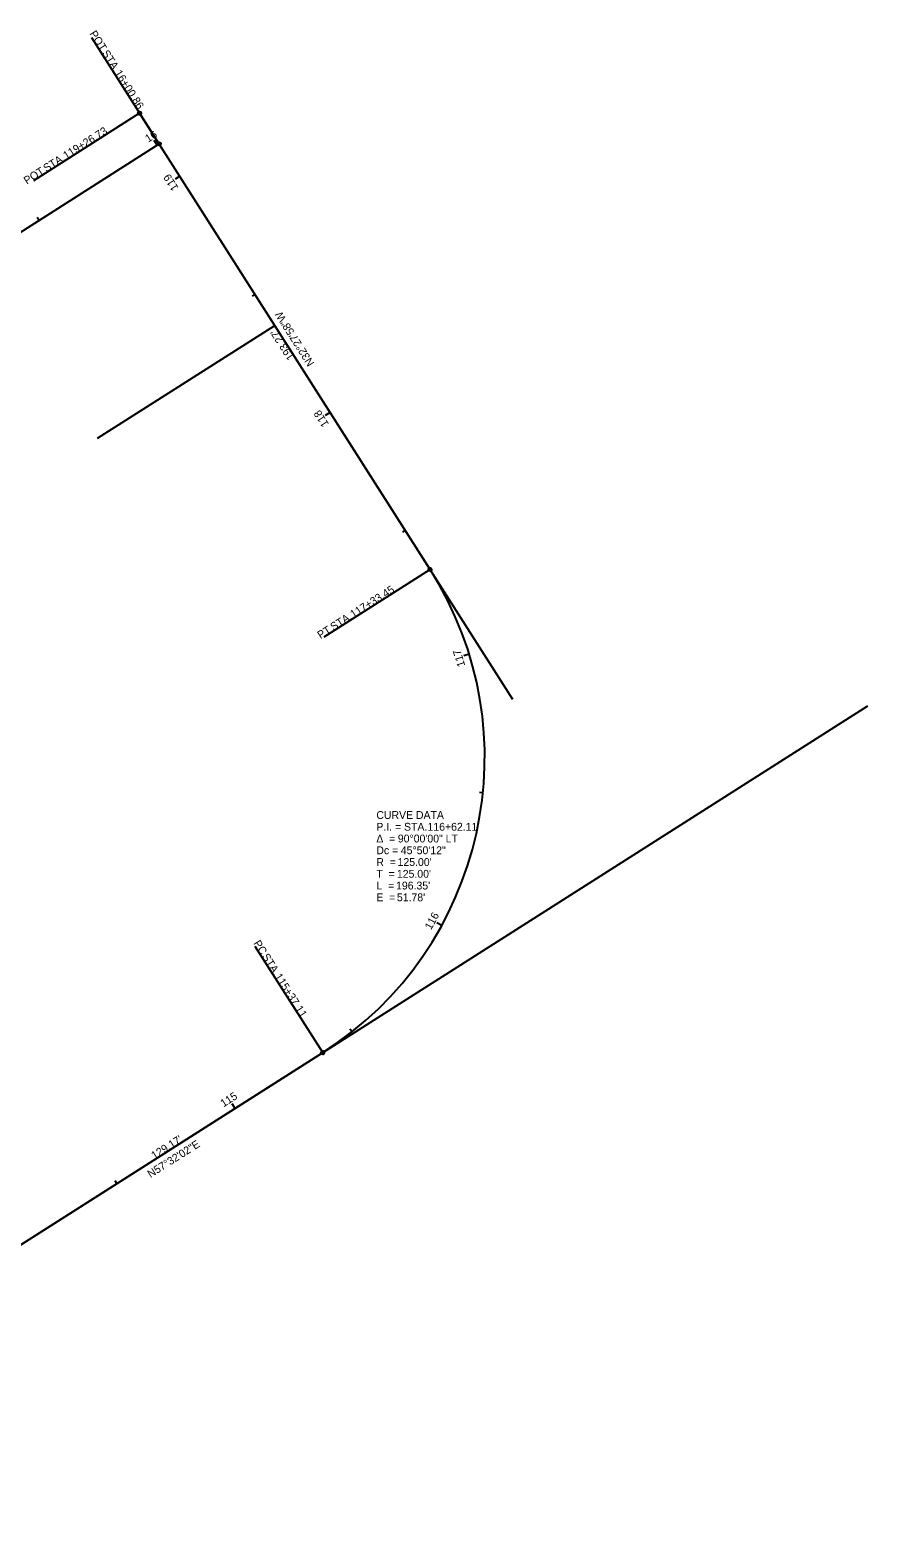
# Model space of a CAD drawing. Extents: x 143938 to 145591, y 512467 to 513276.
# Drawn here: x 145292 to 145591, y 512738 to 513276 of the extents above; entities that cross this region are included whole.
import ezdxf

# ---------------------------------------------------------------- set-up
doc = ezdxf.new("R2010")
doc.units = 0
for name, color, linetype in [('GE_P_Alignment', 7, 'Continuous'), ('GE_P_Alignment_100_Bearings', 7, 'Continuous'), ('GE_P_Alignment_100_Cardinal_Points', 7, 'Continuous'), ('GE_P_Alignment_100_Curve_Data', 7, 'Continuous'), ('GE_P_Alignment_100_Distances', 7, 'Continuous'), ('GE_P_Alignment_100_Stations', 7, 'Continuous'), ('GE_P_Driveway_CL', 7, 'Continuous')]:
    doc.layers.add(name, color=color, linetype=linetype)

msp = doc.modelspace()

# ---------------------------------------------------------------- linework, layer by layer
at = {"layer": 'GE_P_Alignment'}
for p, q in [((145464.37, 513037.37), (145331.09, 513246.84)), ((145434.84, 513083.78), (145331.09, 513246.84)), ((144913.21, 512965.47), (145338.11, 513235.81)), ((145124.06, 512737.89), (145591.23, 513035.12)), ((145287.5, 512841.88), (145396.48, 512911.21))]:
    msp.add_line(p, q, dxfattribs=at)
msp.add_arc((145329.38, 513016.68), 125, 302.4662, 32.4662, dxfattribs=at)
msp.add_arc((145329.38, 513016.68), 125, 302.4662, 32.4662, dxfattribs=at)
at = {"layer": 'GE_P_Alignment_100_Cardinal_Points'}
for p, q in [((145338.11, 513235.81), (145313.96, 513273.78)), ((145331.09, 513246.84), (145293.13, 513222.69)), ((145434.84, 513083.78), (145396.87, 513059.62)), ((145396.48, 512911.21), (145372.32, 512949.18))]:
    msp.add_line(p, q, dxfattribs=at)
for centre in [(145331.09, 513246.84), (145338.11, 513235.81), (145434.84, 513083.78), (145396.48, 512911.21)]:
    msp.add_circle(centre, 0.6, dxfattribs=at)
at = {"layer": 'GE_P_Alignment_100_Stations'}
for p, q in [((145337.38, 513235.34), (145336.31, 513237.03)), ((145345.44, 513224.29), (145343.75, 513223.22)), ((145295.2, 513208.5), (145294.55, 513209.52)), ((145372.28, 513182.11), (145371.27, 513181.46)), ((145399.12, 513139.92), (145397.43, 513138.85)), ((145425.96, 513097.74), (145424.95, 513097.09)), ((145448.83, 513053.5), (145446.92, 513052.91)), ((145453.74, 513004.07), (145452.55, 513004.19)), ((145439.02, 512956.64), (145437.26, 512957.6)), ((145406.98, 512918.68), (145406.24, 512919.62)), ((145365.17, 512891.3), (145364.1, 512892.98)), ((145322.99, 512864.46), (145322.34, 512865.47))]:
    msp.add_line(p, q, dxfattribs=at)
at = {"layer": 'GE_P_Driveway_CL'}
msp.add_line((145316.06, 513130.75), (145379.34, 513171.01), dxfattribs=at)

# ---------------------------------------------------------------- texts
at = {"layer": 'GE_P_Alignment_100_Bearings'}
for s, rotation, p in [('N32°27\'58"W', 122.4662, (145393.63, 513157.5)), ('N57°32\'02"E', 32.4662, (145334.98, 512866.4))]:
    msp.add_text(s, height=2.8, rotation=rotation, dxfattribs=at).set_placement(p)
at = {"layer": 'GE_P_Alignment_100_Cardinal_Points'}
for s, rotation, p in [('POT', 302.4662, (145313.08, 513275.23)), (' STA. ', 302.4662, (145316.95, 513269.15)), ('16+00.86', 302.4662, (145322.02, 513261.18)), ('119+26.73', 32.4662, (145304.85, 513230.2)), (' STA. ', 32.4662, (145296.88, 513225.13)), ('POT', 32.4662, (145290.8, 513221.26)), ('117+33.45', 32.4662, (145407.4, 513066.37)), ('PT', 32.4662, (145395.7, 513058.92)), (' STA. ', 32.4662, (145399.43, 513061.29)), ('PC', 302.4662, (145371.66, 512950.3)), (' STA. ', 302.4662, (145374.12, 512946.43)), ('115+37.11', 302.4662, (145379.2, 512938.45))]:
    msp.add_text(s, height=2.8, rotation=rotation, dxfattribs=at).set_placement(p)
at = {"layer": 'GE_P_Alignment_100_Curve_Data'}
for s, p in [('CURVE DATA', (145415.66, 512994.7)), ('P.I. = STA. ', (145415.66, 512990.5)), ('116+62.11', (145433.93, 512990.5)), ('Δ  = ', (145415.66, 512986.3)), ('90°00\'00" LT', (145423.34, 512986.3)), ('Dc = ', (145415.66, 512982.1)), ('45°50\'12"', (145424.4, 512982.1)), ('R  = ', (145415.66, 512977.9)), ("125.00'", (145423.24, 512977.9)), ('T  = ', (145415.66, 512973.7)), ('L  = ', (145415.66, 512969.5)), ("196.35'", (145422.7, 512969.5)), ("125.00'", (145423, 512973.7)), ('E  = ', (145415.66, 512965.3)), ("51.78'", (145423, 512965.3))]:
    msp.add_text(s, height=2.8, dxfattribs=at).set_placement(p)
at = {"layer": 'GE_P_Alignment_100_Distances'}
for s, rotation, p in [("193.27'", 122.4662, (145386.52, 513159.65)), ("129.17'", 32.4662, (145336.33, 512872.99))]:
    msp.add_text(s, height=2.8, rotation=rotation, dxfattribs=at).set_placement(p)
at = {"layer": 'GE_P_Alignment_100_Stations'}
for s, rotation, p in [('16', 32.4662, (145334.15, 513236.25)), ('119', 122.4662, (145345.11, 513220.15)), ('118', 122.4662, (145398.8, 513135.77)), ('117', 107.1315, (145447.45, 513049.5)), ('116', 61.2949, (145435.21, 512954.89)), ('115', 32.4662, (145361.04, 512891.63))]:
    msp.add_text(s, height=2.8, rotation=rotation, dxfattribs=at).set_placement(p)

doc.saveas('drawing.dxf')
